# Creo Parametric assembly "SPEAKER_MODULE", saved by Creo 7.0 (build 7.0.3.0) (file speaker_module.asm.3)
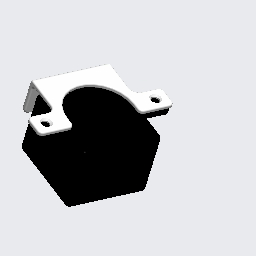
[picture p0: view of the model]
Units: millimeter Kilogram Sec (mmKs); MM, KILOGRAM, SECS

Created from: XX_MMKS_ASM_DESIGN_ABS.ASM

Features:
  1. datum plane "ASM_RIGHT"
  2. datum plane "ASM_TOP"
  3. datum plane "ASM_FRONT"
  4. coordinate system
  5. component "SPEAKER_SET"
  6. component "SPEAKER"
